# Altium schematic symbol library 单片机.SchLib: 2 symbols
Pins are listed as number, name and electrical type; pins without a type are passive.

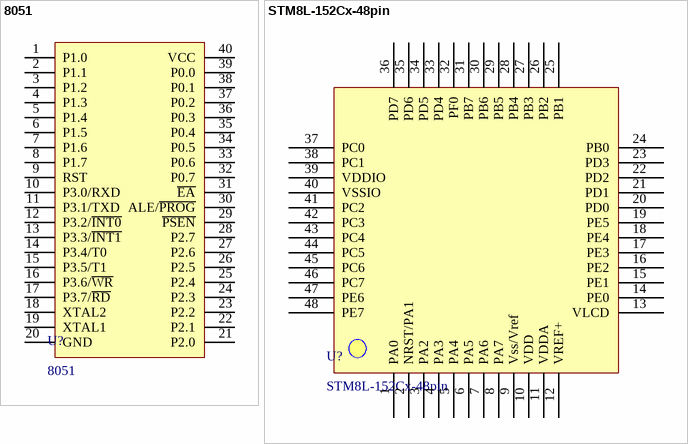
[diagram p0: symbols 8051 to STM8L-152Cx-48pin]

## 8051
designator U?
pins: 1 P1.0, 2 P1.1, 3 P1.2, 4 P1.3, 5 P1.4, 6 P1.5, 7 P1.6, 8 P1.7, 9 RST, 10 P3.0/RXD, 11 P3.1/TXD, 12 P3.2/~{INT0}, 13 P3.3/~{INT1}, 14 P3.4/T0, 15 P3.5/T1, 16 P3.6/~{WR}, 17 P3.7/~{RD}, 18 XTAL2, 19 XTAL1, 20 GND, 21 P2.0, 22 P2.1, 23 P2.2, 24 P2.3, 25 P2.4, 26 P2.5, 27 P2.6, 28 P2.7, 29 ~{PSEN}, 30 ALE/~{PROG}, 31 ~{EA}, 32 P0.7, 33 P0.6, 34 P0.5, 35 P0.4, 36 P0.3, 37 P0.2, 38 P0.1, 39 P0.0, 40 VCC

## STM8L-152Cx-48pin
designator U?
pins: 1 PA0, 2 NRST/PA1, 3 PA2, 4 PA3, 5 PA4, 6 PA5, 7 PA6, 8 PA7, 9 Vss/Vref, 10 VDD, 11 VDDA, 12 VREF+, 13 VLCD, 14 PE0, 15 PE1, 16 PE2, 17 PE3, 18 PE4, 19 PE5, 20 PD0, 21 PD1, 22 PD2, 23 PD3, 24 PB0, 25 PB1, 26 PB2, 27 PB3, 28 PB4, 29 PB5, 30 PB6, 31 PB7, 32 PF0, 33 PD4, 34 PD5, 35 PD6, 36 PD7, 37 PC0, 38 PC1, 39 VDDIO, 40 VSSIO, 41 PC2, 42 PC3, 43 PC4, 44 PC5, 45 PC6, 46 PC7, 47 PE6, 48 PE7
